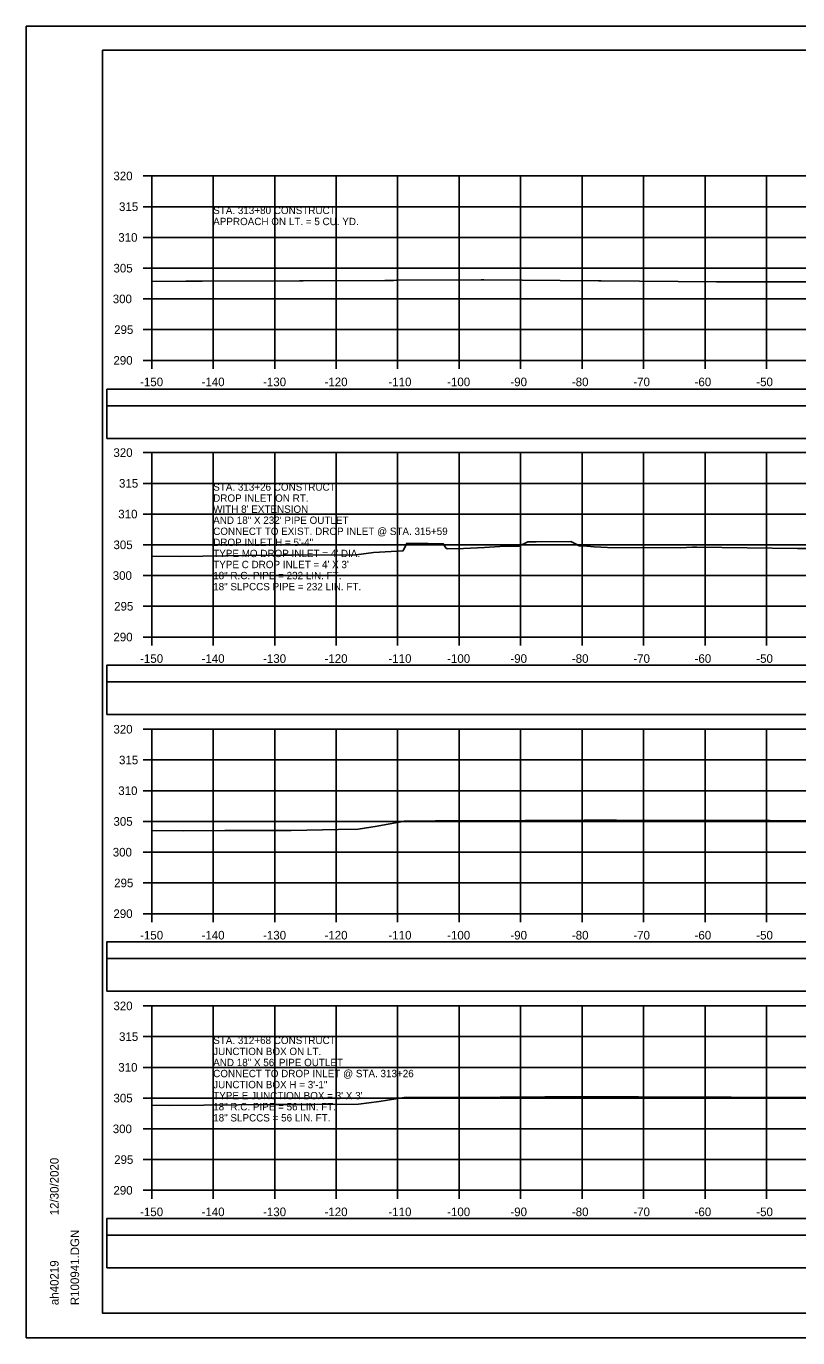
# Model space of a CAD drawing. Extents: x 1370538 to 1372872, y 376220 to 381127.
# Drawn here: x 1371204.9 to 1371330.4, y 378049.2 to 378262.5 of the extents above; entities that cross this region are included whole.
import ezdxf

# ---------------------------------------------------------------- set-up
doc = ezdxf.new("R2010")
doc.units = 0
for name, color, linetype in [('R_Border Notes', 7, 'Continuous'), ('R_Border PE', 7, 'Continuous'), ('R_Border Prem', 7, 'Continuous'), ('R_Dimension', 7, 'Continuous'), ('R_Grid', 7, 'Continuous'), ('R_Horz Alg Annot', 7, 'Continuous'), ('R_No Plot', 7, 'Continuous'), ('R_Water Annot', 7, 'Continuous')]:
    doc.layers.add(name, color=color, linetype=linetype)

msp = doc.modelspace()

# ---------------------------------------------------------------- linework, layer by layer
at = {"layer": 'R_Border Notes'}
for p, q in [((1371217.29, 378258.65), (1371533.47, 378258.65)), ((1371217.29, 378053.19), (1371217.29, 378258.65)), ((1371217.29, 378053.19), (1371217.29, 378053.19)), ((1371533.47, 378053.19), (1371217.29, 378053.19))]:
    msp.add_line(p, q, dxfattribs=at)
at = {"layer": 'R_Border Prem'}
for p, q in [((1371223.89, 378238.19), (1371225.29, 378238.19)), ((1371225.29, 378208.19), (1371225.29, 378238.19)), ((1371223.89, 378233.19), (1371225.29, 378233.19)), ((1371223.89, 378228.19), (1371225.29, 378228.19)), ((1371223.89, 378223.19), (1371225.29, 378223.19)), ((1371223.89, 378218.19), (1371225.29, 378218.19)), ((1371223.89, 378213.19), (1371225.29, 378213.19)), ((1371223.89, 378208.19), (1371225.29, 378208.19)), ((1371225.29, 378208.19), (1371525.29, 378208.19)), ((1371225.29, 378206.79), (1371225.29, 378208.19)), ((1371235.29, 378206.79), (1371235.29, 378208.19)), ((1371245.29, 378206.79), (1371245.29, 378208.19)), ((1371255.29, 378206.79), (1371255.29, 378208.19)), ((1371265.29, 378206.79), (1371265.29, 378208.19)), ((1371275.29, 378206.79), (1371275.29, 378208.19)), ((1371285.29, 378206.79), (1371285.29, 378208.19)), ((1371295.29, 378206.79), (1371295.29, 378208.19)), ((1371305.29, 378206.79), (1371305.29, 378208.19)), ((1371315.29, 378206.79), (1371315.29, 378208.19)), ((1371325.29, 378206.79), (1371325.29, 378208.19)), ((1371223.89, 378193.19), (1371225.29, 378193.19)), ((1371225.29, 378163.19), (1371225.29, 378193.19)), ((1371223.89, 378188.19), (1371225.29, 378188.19)), ((1371223.89, 378183.19), (1371225.29, 378183.19)), ((1371223.89, 378178.19), (1371225.29, 378178.19)), ((1371223.89, 378173.19), (1371225.29, 378173.19)), ((1371223.89, 378168.19), (1371225.29, 378168.19)), ((1371223.89, 378163.19), (1371225.29, 378163.19)), ((1371225.29, 378163.19), (1371525.29, 378163.19)), ((1371225.29, 378161.79), (1371225.29, 378163.19)), ((1371235.29, 378161.79), (1371235.29, 378163.19)), ((1371245.29, 378161.79), (1371245.29, 378163.19)), ((1371255.29, 378161.79), (1371255.29, 378163.19)), ((1371265.29, 378161.79), (1371265.29, 378163.19)), ((1371275.29, 378161.79), (1371275.29, 378163.19)), ((1371285.29, 378161.79), (1371285.29, 378163.19)), ((1371295.29, 378161.79), (1371295.29, 378163.19)), ((1371305.29, 378161.79), (1371305.29, 378163.19)), ((1371315.29, 378161.79), (1371315.29, 378163.19)), ((1371325.29, 378161.79), (1371325.29, 378163.19)), ((1371223.89, 378148.19), (1371225.29, 378148.19)), ((1371225.29, 378118.19), (1371225.29, 378148.19)), ((1371223.89, 378143.19), (1371225.29, 378143.19)), ((1371223.89, 378138.19), (1371225.29, 378138.19)), ((1371223.89, 378133.19), (1371225.29, 378133.19)), ((1371223.89, 378128.19), (1371225.29, 378128.19)), ((1371223.89, 378123.19), (1371225.29, 378123.19)), ((1371223.89, 378118.19), (1371225.29, 378118.19)), ((1371225.29, 378118.19), (1371525.29, 378118.19)), ((1371225.29, 378116.79), (1371225.29, 378118.19)), ((1371235.29, 378116.79), (1371235.29, 378118.19)), ((1371245.29, 378116.79), (1371245.29, 378118.19)), ((1371255.29, 378116.79), (1371255.29, 378118.19)), ((1371265.29, 378116.79), (1371265.29, 378118.19)), ((1371275.29, 378116.79), (1371275.29, 378118.19)), ((1371285.29, 378116.79), (1371285.29, 378118.19)), ((1371295.29, 378116.79), (1371295.29, 378118.19)), ((1371305.29, 378116.79), (1371305.29, 378118.19)), ((1371315.29, 378116.79), (1371315.29, 378118.19)), ((1371325.29, 378116.79), (1371325.29, 378118.19)), ((1371223.89, 378103.19), (1371225.29, 378103.19)), ((1371225.29, 378073.19), (1371225.29, 378103.19)), ((1371223.89, 378098.19), (1371225.29, 378098.19)), ((1371223.89, 378093.19), (1371225.29, 378093.19)), ((1371223.89, 378088.19), (1371225.29, 378088.19)), ((1371223.89, 378083.19), (1371225.29, 378083.19)), ((1371223.89, 378078.19), (1371225.29, 378078.19)), ((1371223.89, 378073.19), (1371225.29, 378073.19)), ((1371225.29, 378073.19), (1371525.29, 378073.19)), ((1371225.29, 378071.79), (1371225.29, 378073.19)), ((1371235.29, 378071.79), (1371235.29, 378073.19)), ((1371245.29, 378071.79), (1371245.29, 378073.19)), ((1371255.29, 378071.79), (1371255.29, 378073.19)), ((1371265.29, 378071.79), (1371265.29, 378073.19)), ((1371275.29, 378071.79), (1371275.29, 378073.19)), ((1371285.29, 378071.79), (1371285.29, 378073.19)), ((1371295.29, 378071.79), (1371295.29, 378073.19)), ((1371305.29, 378071.79), (1371305.29, 378073.19)), ((1371315.29, 378071.79), (1371315.29, 378073.19)), ((1371325.29, 378071.79), (1371325.29, 378073.19))]:
    msp.add_line(p, q, dxfattribs=at)
at = {"layer": 'R_Dimension'}
for points in [[(1371225.29, 378221.04), (1371230.83, 378221.06), (1371233.49, 378221.06), (1371249.32, 378221.13), (1371249.62, 378221.14), (1371249.94, 378221.14), (1371263.2, 378221.2), (1371264.6, 378221.21), (1371265.08, 378221.22), (1371278.87, 378221.28), (1371279.12, 378221.28), (1371279.31, 378221.28), (1371297.96, 378221.13), (1371298.12, 378221.13), (1371298.39, 378221.13), (1371317.18, 378220.98), (1371317.51, 378220.98), (1371317.56, 378220.98), (1371333.42, 378220.96)], [(1371225.29, 378176.35), (1371229.81, 378176.3), (1371241.16, 378176.43), (1371246.81, 378176.48), (1371248.1, 378176.48), (1371258.52, 378176.54), (1371261.39, 378176.96), (1371266.14, 378177.21), (1371266.3, 378177.44), (1371266.8, 378178.45), (1371270.25, 378178.42), (1371272.71, 378178.36), (1371273.13, 378177.69), (1371273.37, 378177.53), (1371275.99, 378177.59), (1371279.42, 378177.75), (1371281.91, 378177.92), (1371285.03, 378177.98), (1371286.25, 378178.55), (1371286.48, 378178.65), (1371287.82, 378178.65), (1371293.44, 378178.73), (1371294.24, 378178.35), (1371294.82, 378178.03), (1371295.47, 378178.01), (1371297.27, 378177.84), (1371299.44, 378177.76), (1371311.3, 378177.71), (1371313.24, 378177.81), (1371313.96, 378177.82), (1371330.36, 378177.6), (1371336.83, 378177.58)], [(1371225.29, 378131.71), (1371230.45, 378131.69), (1371237.2, 378131.7), (1371248, 378131.73), (1371255.61, 378131.88), (1371258.85, 378131.92), (1371261.94, 378132.45), (1371266.39, 378133.25), (1371271.43, 378133.28), (1371276.39, 378133.29), (1371295.62, 378133.39), (1371300.88, 378133.39), (1371321.1, 378133.32), (1371325.83, 378133.33), (1371331.9, 378133.31)], [(1371225.29, 378087.03), (1371228.13, 378087.01), (1371245.04, 378087.15), (1371249.27, 378087.17), (1371251.64, 378087.17), (1371258.93, 378087.22), (1371262.29, 378087.63), (1371266.37, 378088.29), (1371267.24, 378088.3), (1371272.19, 378088.29), (1371281.99, 378088.36), (1371289.22, 378088.4), (1371304.46, 378088.38), (1371312.52, 378088.35), (1371319.56, 378088.32), (1371325.69, 378088.3), (1371331.82, 378088.28)]]:
    msp.add_lwpolyline(points, dxfattribs=at)
at = {"layer": 'R_Grid'}
for p, q in [((1371225.29, 378238.19), (1371525.29, 378238.19)), ((1371225.29, 378208.19), (1371225.29, 378238.19)), ((1371235.29, 378208.19), (1371235.29, 378238.19)), ((1371245.29, 378208.19), (1371245.29, 378238.19)), ((1371255.29, 378208.19), (1371255.29, 378238.19)), ((1371265.29, 378208.19), (1371265.29, 378238.19)), ((1371275.29, 378208.19), (1371275.29, 378238.19)), ((1371285.29, 378208.19), (1371285.29, 378238.19)), ((1371295.29, 378208.19), (1371295.29, 378238.19)), ((1371305.29, 378208.19), (1371305.29, 378238.19)), ((1371315.29, 378208.19), (1371315.29, 378238.19)), ((1371325.29, 378208.19), (1371325.29, 378238.19)), ((1371225.29, 378233.19), (1371525.29, 378233.19)), ((1371225.29, 378228.19), (1371525.29, 378228.19)), ((1371225.29, 378223.19), (1371525.29, 378223.19)), ((1371225.29, 378218.19), (1371525.29, 378218.19)), ((1371225.29, 378213.19), (1371525.29, 378213.19)), ((1371225.29, 378208.19), (1371525.29, 378208.19)), ((1371225.29, 378193.19), (1371525.29, 378193.19)), ((1371225.29, 378163.19), (1371225.29, 378193.19)), ((1371235.29, 378163.19), (1371235.29, 378193.19)), ((1371245.29, 378163.19), (1371245.29, 378193.19)), ((1371255.29, 378163.19), (1371255.29, 378193.19)), ((1371265.29, 378163.19), (1371265.29, 378193.19)), ((1371275.29, 378163.19), (1371275.29, 378193.19)), ((1371285.29, 378163.19), (1371285.29, 378193.19)), ((1371295.29, 378163.19), (1371295.29, 378193.19)), ((1371305.29, 378163.19), (1371305.29, 378193.19)), ((1371315.29, 378163.19), (1371315.29, 378193.19)), ((1371325.29, 378163.19), (1371325.29, 378193.19)), ((1371225.29, 378188.19), (1371525.29, 378188.19)), ((1371225.29, 378183.19), (1371525.29, 378183.19)), ((1371225.29, 378178.19), (1371525.29, 378178.19)), ((1371225.29, 378173.19), (1371525.29, 378173.19)), ((1371225.29, 378168.19), (1371525.29, 378168.19)), ((1371225.29, 378163.19), (1371525.29, 378163.19)), ((1371225.29, 378148.19), (1371525.29, 378148.19)), ((1371225.29, 378118.19), (1371225.29, 378148.19)), ((1371235.29, 378118.19), (1371235.29, 378148.19)), ((1371245.29, 378118.19), (1371245.29, 378148.19)), ((1371255.29, 378118.19), (1371255.29, 378148.19)), ((1371265.29, 378118.19), (1371265.29, 378148.19)), ((1371275.29, 378118.19), (1371275.29, 378148.19)), ((1371285.29, 378118.19), (1371285.29, 378148.19)), ((1371295.29, 378118.19), (1371295.29, 378148.19)), ((1371305.29, 378118.19), (1371305.29, 378148.19)), ((1371315.29, 378118.19), (1371315.29, 378148.19)), ((1371325.29, 378118.19), (1371325.29, 378148.19)), ((1371225.29, 378143.19), (1371525.29, 378143.19)), ((1371225.29, 378138.19), (1371525.29, 378138.19)), ((1371225.29, 378133.19), (1371525.29, 378133.19)), ((1371225.29, 378128.19), (1371525.29, 378128.19)), ((1371225.29, 378123.19), (1371525.29, 378123.19)), ((1371225.29, 378118.19), (1371525.29, 378118.19)), ((1371225.29, 378103.19), (1371525.29, 378103.19)), ((1371225.29, 378073.19), (1371225.29, 378103.19)), ((1371235.29, 378073.19), (1371235.29, 378103.19)), ((1371245.29, 378073.19), (1371245.29, 378103.19)), ((1371255.29, 378073.19), (1371255.29, 378103.19)), ((1371265.29, 378073.19), (1371265.29, 378103.19)), ((1371275.29, 378073.19), (1371275.29, 378103.19)), ((1371285.29, 378073.19), (1371285.29, 378103.19)), ((1371295.29, 378073.19), (1371295.29, 378103.19)), ((1371305.29, 378073.19), (1371305.29, 378103.19)), ((1371315.29, 378073.19), (1371315.29, 378103.19)), ((1371325.29, 378073.19), (1371325.29, 378103.19)), ((1371225.29, 378098.19), (1371525.29, 378098.19)), ((1371225.29, 378093.19), (1371525.29, 378093.19)), ((1371225.29, 378088.19), (1371525.29, 378088.19)), ((1371225.29, 378083.19), (1371525.29, 378083.19)), ((1371225.29, 378078.19), (1371525.29, 378078.19)), ((1371225.29, 378073.19), (1371525.29, 378073.19))]:
    msp.add_line(p, q, dxfattribs=at)
at = {"layer": 'R_Horz Alg Annot'}
for points in [[(1371218, 378200.78), (1371533.13, 378200.78), (1371533.13, 378203.49), (1371218, 378203.49)], [(1371218, 378195.46), (1371533.13, 378195.46), (1371533.13, 378200.78), (1371218, 378200.78)], [(1371218, 378155.92), (1371533.13, 378155.92), (1371533.13, 378158.62), (1371218, 378158.62)], [(1371218, 378150.59), (1371533.13, 378150.59), (1371533.13, 378155.92), (1371218, 378155.92)], [(1371218, 378110.91), (1371533.13, 378110.91), (1371533.13, 378113.62), (1371218, 378113.62)], [(1371218, 378105.59), (1371533.13, 378105.59), (1371533.13, 378110.91), (1371218, 378110.91)], [(1371218, 378065.9), (1371533.13, 378065.9), (1371533.13, 378068.61), (1371218, 378068.61)], [(1371218, 378060.58), (1371533.13, 378060.58), (1371533.13, 378065.9), (1371218, 378065.9)]]:
    msp.add_lwpolyline(points, close=True, dxfattribs=at)
at = {"layer": 'R_No Plot'}
for p, q in [((1371204.89, 378262.54), (1371538.22, 378262.54)), ((1371204.89, 378049.21), (1371538.22, 378049.21))]:
    msp.add_line(p, q, dxfattribs=at)
for points in [[(1371204.88, 378262.54), (1371538.22, 378262.54), (1371538.22, 378049.21), (1371204.88, 378049.21)], [(1371451.21, 378258.65), (1371451.21, 378248.77), (1371486.94, 378248.77), (1371486.94, 378245.85), (1371510.14, 378245.85), (1371510.14, 378221.52), (1371533.47, 378221.52), (1371533.47, 378053.19), (1371217.29, 378053.19), (1371217.29, 378258.65)]]:
    msp.add_lwpolyline(points, close=True, dxfattribs=at)

# ---------------------------------------------------------------- texts
at = {"layer": 'R_Border Notes'}
for s, p in [('12/30/2020', (1371210.15, 378069.12)), ('R100941.DGN', (1371213.48, 378054.51)), ('ah40219', (1371210.15, 378054.51))]:
    msp.add_text(s, height=1.4, rotation=90, dxfattribs=at).set_placement(p)
at = {"layer": 'R_Border PE'}
for s, p in [('320', (1371219.06, 378237.49)), ('315', (1371219.97, 378232.49)), ('310', (1371219.85, 378227.49)), ('305', (1371219.07, 378222.49)), ('300', (1371218.95, 378217.49)), ('295', (1371219.18, 378212.49)), ('290', (1371219.06, 378207.49)), ('-150', (1371223.4, 378203.99)), ('-140', (1371233.4, 378203.99)), ('-130', (1371243.4, 378203.99)), ('-120', (1371253.4, 378203.99)), ('-110', (1371263.79, 378203.99)), ('-100', (1371273.34, 378203.99)), ('-90', (1371283.63, 378203.99)), ('-80', (1371293.63, 378203.99)), ('-70', (1371303.63, 378203.99)), ('-60', (1371313.59, 378203.99)), ('-50', (1371323.63, 378203.99)), ('320', (1371219.06, 378192.49)), ('315', (1371219.97, 378187.49)), ('310', (1371219.85, 378182.49)), ('305', (1371219.07, 378177.49)), ('300', (1371218.95, 378172.49)), ('295', (1371219.18, 378167.49)), ('290', (1371219.06, 378162.49)), ('-150', (1371223.4, 378158.99)), ('-140', (1371233.4, 378158.99)), ('-130', (1371243.4, 378158.99)), ('-120', (1371253.4, 378158.99)), ('-110', (1371263.79, 378158.99)), ('-100', (1371273.34, 378158.99)), ('-90', (1371283.63, 378158.99)), ('-80', (1371293.63, 378158.99)), ('-70', (1371303.63, 378158.99)), ('-60', (1371313.59, 378158.99)), ('-50', (1371323.63, 378158.99)), ('320', (1371219.06, 378147.49)), ('315', (1371219.97, 378142.49)), ('310', (1371219.85, 378137.49)), ('305', (1371219.07, 378132.49)), ('300', (1371218.95, 378127.49)), ('295', (1371219.18, 378122.49)), ('290', (1371219.06, 378117.49)), ('-150', (1371223.4, 378113.99)), ('-140', (1371233.4, 378113.99)), ('-130', (1371243.4, 378113.99)), ('-120', (1371253.4, 378113.99)), ('-110', (1371263.79, 378113.99)), ('-100', (1371273.34, 378113.99)), ('-90', (1371283.63, 378113.99)), ('-80', (1371293.63, 378113.99)), ('-70', (1371303.63, 378113.99)), ('-60', (1371313.59, 378113.99)), ('-50', (1371323.63, 378113.99)), ('320', (1371219.06, 378102.49)), ('315', (1371219.97, 378097.49)), ('310', (1371219.85, 378092.49)), ('305', (1371219.07, 378087.49)), ('300', (1371218.95, 378082.49)), ('295', (1371219.18, 378077.49)), ('290', (1371219.06, 378072.49)), ('-150', (1371223.4, 378068.99)), ('-140', (1371233.4, 378068.99)), ('-130', (1371243.4, 378068.99)), ('-120', (1371253.4, 378068.99)), ('-110', (1371263.79, 378068.99)), ('-100', (1371273.34, 378068.99)), ('-90', (1371283.63, 378068.99)), ('-80', (1371293.63, 378068.99)), ('-70', (1371303.63, 378068.99)), ('-60', (1371313.59, 378068.99)), ('-50', (1371323.63, 378068.99))]:
    msp.add_text(s, height=1.4, dxfattribs=at).set_placement(p)
at = {"layer": 'R_Water Annot'}
for s, p in [('STA. 313+80 CONSTRUCT', (1371235.29, 378231.99)), ('APPROACH ON LT. = 5 CU. YD.', (1371235.29, 378230.19)), ('STA. 313+26 CONSTRUCT', (1371235.29, 378186.99)), ('DROP INLET ON RT.', (1371235.29, 378185.19)), ("WITH 8' EXTENSION", (1371235.29, 378183.39)), ('AND 18" X 232\' PIPE OUTLET', (1371235.29, 378181.59)), ('CONNECT TO EXIST. DROP INLET @ STA. 315+59', (1371235.29, 378179.79)), ("TYPE MO DROP INLET = 4' DIA.", (1371235.29, 378176.19)), ('DROP INLET H = 5\'-4"', (1371235.29, 378177.99)), ("TYPE C DROP INLET = 4' X 3'", (1371235.29, 378174.39)), ('18" R.C. PIPE = 232 LIN. FT.', (1371235.29, 378172.59)), ('18" SLPCCS PIPE = 232 LIN. FT.', (1371235.29, 378170.79)), ('JUNCTION BOX ON LT.', (1371235.29, 378095.19)), ('STA. 312+68 CONSTRUCT', (1371235.29, 378096.99)), ('AND 18" X 56\' PIPE OUTLET', (1371235.29, 378093.39)), ('CONNECT TO DROP INLET @ STA. 313+26', (1371235.29, 378091.59)), ('JUNCTION BOX H = 3\'-1"', (1371235.29, 378089.79)), ("TYPE E JUNCTION BOX = 3' X 3'", (1371235.29, 378087.99)), ('18" R.C. PIPE = 56 LIN. FT.', (1371235.29, 378086.19)), ('18" SLPCCS = 56 LIN. FT.', (1371235.29, 378084.39))]:
    msp.add_text(s, height=1.2, dxfattribs=at).set_placement(p)

doc.saveas('drawing.dxf')
